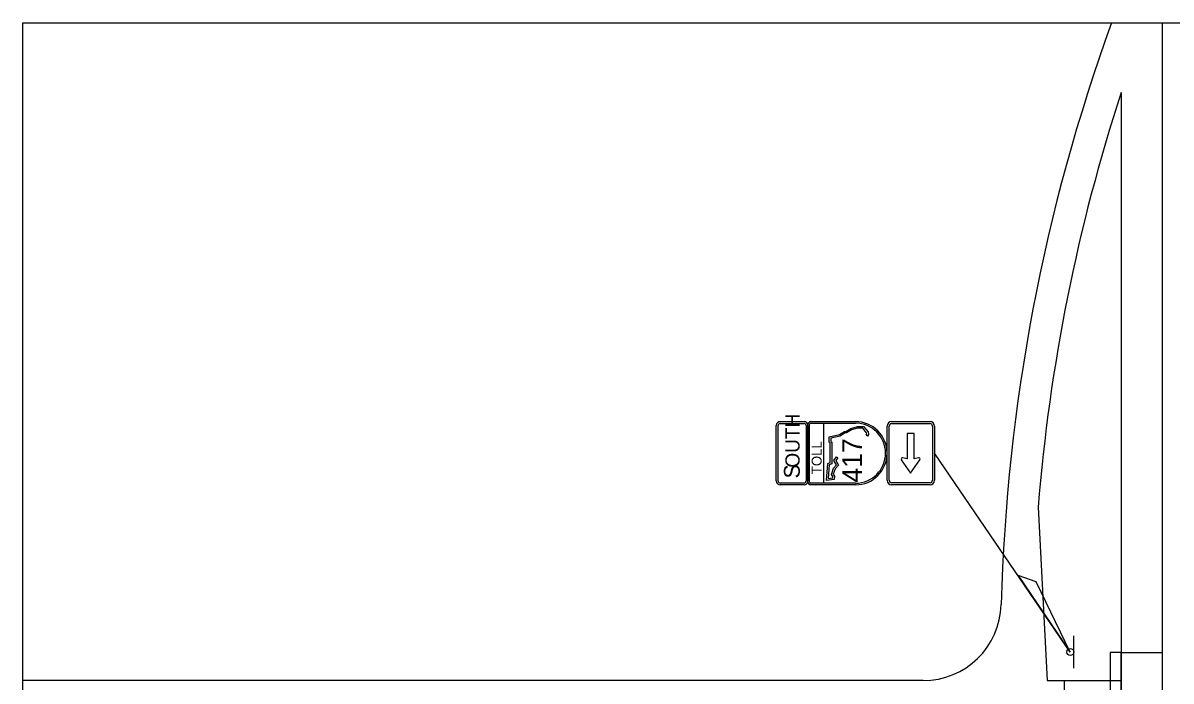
# Model space of a CAD drawing. Extents: x -830008.4 to -829992.7, y 1290284.1 to 1290294.4.
# Drawn here: x -830007.47 to -830000.13, y 1290290.01 to 1290294.23 of the extents above; entities that cross this region are included whole.
import ezdxf

# ---------------------------------------------------------------- set-up
doc = ezdxf.new("R2010")
doc.units = 0
for name, color, linetype in [('LeaderLine_dp', 7, 'Continuous'), ('NonPlottingEle_dp', 7, 'Continuous'), ('SignPanel', 7, 'Continuous'), ('SignSupport', 7, 'Continuous'), ('TextLabel', 7, 'Continuous')]:
    doc.layers.add(name, color=color, linetype=linetype)

msp = doc.modelspace()

# ---------------------------------------------------------------- linework, layer by layer
at = {"layer": 'LeaderLine_dp'}
for p, q in [((-830000.9905, 1290290.6499), (-830001.1075, 1290290.6898)), ((-830001.1075, 1290290.6898), (-830000.7731, 1290290.1996)), ((-830000.7731, 1290290.1996), (-830000.9905, 1290290.6499))]:
    msp.add_line(p, q, dxfattribs=at)
at = {"layer": 'NonPlottingEle_dp'}
msp.add_lwpolyline([(-830007.4742, 1290294.228), (-829992.7742, 1290294.228), (-829992.7742, 1290285.328), (-830007.4742, 1290285.328)], close=True, dxfattribs=at)
at = {"layer": 'SignPanel'}
for p, q in [((-830002.2504, 1290291.5919), (-830002.217, 1290291.6127)), ((-830002.217, 1290291.6127), (-830002.2086, 1290291.6127)), ((-830002.2086, 1290291.6127), (-830002.1776, 1290291.6315)), ((-830002.1734, 1290291.6217), (-830002.2056, 1290291.6021)), ((-830002.1776, 1290291.6315), (-830002.1352, 1290291.6431)), ((-830002.1338, 1290291.6325), (-830002.1734, 1290291.6217)), ((-830002.1352, 1290291.6431), (-830002.0956, 1290291.6431)), ((-830002.1006, 1290291.6325), (-830002.1338, 1290291.6325)), ((-830002.077, 1290291.6037), (-830002.1006, 1290291.6325)), ((-830002.0956, 1290291.6431), (-830002.0673, 1290291.6085)), ((-830002.0673, 1290291.6085), (-830002.0634, 1290291.5921)), ((-830002.3162, 1290291.5766), (-830002.2504, 1290291.5919)), ((-830002.3162, 1290291.5428), (-830002.3162, 1290291.5766)), ((-830002.3092, 1290291.5381), (-830002.3162, 1290291.5428)), ((-830002.3092, 1290291.4127), (-830002.3092, 1290291.5381)), ((-830002.2464, 1290291.582), (-830002.3056, 1290291.5682)), ((-830002.3056, 1290291.5682), (-830002.3056, 1290291.5484)), ((-830002.3056, 1290291.5484), (-830002.2987, 1290291.5437)), ((-830002.2987, 1290291.5437), (-830002.2987, 1290291.4055)), ((-830002.214, 1290291.6021), (-830002.2464, 1290291.582)), ((-830002.2056, 1290291.6021), (-830002.214, 1290291.6021)), ((-830002.0793, 1290291.5877), (-830002.0747, 1290291.5942)), ((-830002.0706, 1290291.5817), (-830002.0793, 1290291.5877)), ((-830002.0747, 1290291.5942), (-830002.077, 1290291.6037)), ((-830002.0634, 1290291.5921), (-830002.0706, 1290291.5817)), ((-830001.8177, 1290291.5985), (-830001.8177, 1290291.4361)), ((-830001.7722, 1290291.5985), (-830001.8177, 1290291.5985)), ((-830001.7722, 1290291.4361), (-830001.7722, 1290291.5985)), ((-830002.3334, 1290291.2972), (-830002.3249, 1290291.4065)), ((-830002.3249, 1290291.4065), (-830002.3092, 1290291.4127)), ((-830002.3149, 1290291.3991), (-830002.3218, 1290291.3097)), ((-830002.2987, 1290291.4055), (-830002.3149, 1290291.3991)), ((-830002.2878, 1290291.3775), (-830002.2686, 1290291.3982)), ((-830002.2851, 1290291.4262), (-830002.2697, 1290291.4491)), ((-830002.2686, 1290291.3982), (-830002.2851, 1290291.4262)), ((-830002.2556, 1290291.3967), (-830002.2785, 1290291.372)), ((-830002.2609, 1290291.4432), (-830002.2727, 1290291.4258)), ((-830002.2727, 1290291.4258), (-830002.2556, 1290291.3967)), ((-830002.2697, 1290291.4491), (-830002.2609, 1290291.4432)), ((-830001.8542, 1290291.4309), (-830001.7949, 1290291.3447)), ((-830001.8177, 1290291.4361), (-830001.8445, 1290291.4441)), ((-830001.7949, 1290291.3447), (-830001.7357, 1290291.4309)), ((-830001.7454, 1290291.4441), (-830001.7722, 1290291.4361)), ((-830002.3218, 1290291.3097), (-830002.2928, 1290291.3142)), ((-830002.3015, 1290291.3353), (-830002.2878, 1290291.3775)), ((-830002.2918, 1290291.3228), (-830002.3015, 1290291.3353)), ((-830002.2928, 1290291.3142), (-830002.2918, 1290291.3228)), ((-830002.2785, 1290291.372), (-830002.2898, 1290291.3374)), ((-830002.2898, 1290291.3374), (-830002.2808, 1290291.3259)), ((-830002.2808, 1290291.3259), (-830002.2833, 1290291.305)), ((-830002.2833, 1290291.305), (-830002.3334, 1290291.2972))]:
    msp.add_line(p, q, dxfattribs=at)
for points in [[(-830002.654, 1290291.2955), (-830002.654, 1290291.6499)], [(-830002.6424, 1290291.2955), (-830002.6424, 1290291.6499)], [(-830002.6287, 1290291.6752), (-830002.4768, 1290291.6752)], [(-830002.6287, 1290291.6636), (-830002.4768, 1290291.6636)], [(-830002.4631, 1290291.6499), (-830002.4631, 1290291.2955)], [(-830002.4515, 1290291.2871), (-830002.4515, 1290291.6583)], [(-830002.4515, 1290291.6499), (-830002.4515, 1290291.2955)], [(-830002.4414, 1290291.2871), (-830002.4414, 1290291.6583)], [(-830002.4346, 1290291.6752), (-830002.1477, 1290291.6752)], [(-830002.4346, 1290291.6651), (-830002.1477, 1290291.6651)], [(-830002.3502, 1290291.2803), (-830002.3502, 1290291.6651)], [(-830001.9452, 1290291.2991), (-830001.9452, 1290291.6463)], [(-830001.932, 1290291.2991), (-830001.932, 1290291.6463)], [(-830001.9163, 1290291.6752), (-830001.6704, 1290291.6752)], [(-830001.9163, 1290291.6619), (-830001.6704, 1290291.6619)], [(-830001.6548, 1290291.6463), (-830001.6548, 1290291.2991)], [(-830001.6415, 1290291.6463), (-830001.6415, 1290291.2991)], [(-830002.4768, 1290291.2818), (-830002.6287, 1290291.2818)], [(-830002.4768, 1290291.2702), (-830002.6287, 1290291.2702)], [(-830002.1477, 1290291.2803), (-830002.4346, 1290291.2803)], [(-830002.1477, 1290291.2702), (-830002.4346, 1290291.2702)], [(-830001.6704, 1290291.2834), (-830001.9163, 1290291.2834)], [(-830001.6704, 1290291.2702), (-830001.9163, 1290291.2702)]]:
    msp.add_lwpolyline(points, dxfattribs=at)
for centre, radius, start, end in [((-830002.6287, 1290291.6499), 0.0253, 90, 180), ((-830002.6287, 1290291.6499), 0.0137, 90, 180), ((-830002.4768, 1290291.6499), 0.0253, 0, 90), ((-830002.4768, 1290291.6499), 0.0137, 0, 90), ((-830002.4346, 1290291.6583), 0.0169, 90, 180), ((-830002.4346, 1290291.6583), 0.00675, 90, 180), ((-830002.1477, 1290291.4727), 0.2025, 270, 90), ((-830002.1477, 1290291.4727), 0.1924, 270, 90), ((-830001.9163, 1290291.6463), 0.0289, 90, 180), ((-830001.9163, 1290291.6463), 0.0157, 90.0544, 180), ((-830001.6704, 1290291.6463), 0.0289, 0, 90), ((-830001.6704, 1290291.6463), 0.0157, 0, 90), ((-830001.847, 1290291.4358), 0.00868, 73.35571, 214.48807), ((-830001.7429, 1290291.4358), 0.00868, 325.51192, 106.64431), ((-830002.6287, 1290291.2955), 0.0253, 180, 270), ((-830002.6287, 1290291.2955), 0.0137, 180, 270), ((-830002.4768, 1290291.2955), 0.0253, 270, 360), ((-830002.4768, 1290291.2955), 0.0137, 270, 360), ((-830002.4346, 1290291.2871), 0.0169, 180, 270), ((-830002.4346, 1290291.2871), 0.00675, 180, 270), ((-830001.9163, 1290291.2991), 0.0289, 180, 270), ((-830001.9163, 1290291.2991), 0.0157, 180, 269.9456), ((-830001.6704, 1290291.2991), 0.0289, 270, 360), ((-830001.6704, 1290291.2991), 0.0157, 270, 360)]:
    msp.add_arc(centre, radius, start, end, dxfattribs=at)
at = {"layer": 'SignSupport'}
msp.add_line((-830000.7511, 1290290.0967), (-830000.7511, 1290290.3025), dxfattribs=at)
msp.add_circle((-830000.7731, 1290290.1996), 0.0221, dxfattribs=at)
at = {"layer": 'TextLabel'}
for p, q in [((-830000.1852, 1290294.228), (-830000.1852, 1290285.328)), ((-830000.448, 1290293.7828), (-830000.448, 1290288.446)), ((-830000.7731, 1290290.1996), (-830001.6415, 1290291.4727)), ((-830000.9789, 1290291.1282), (-830000.922, 1290290.0166)), ((-830000.448, 1290290.196), (-830000.1852, 1290290.196)), ((-830001.7147, 1290290.0166), (-830007.4742, 1290290.0166)), ((-830000.922, 1290290.0166), (-830000.448, 1290290.0166)), ((-830000.8113, 1290290.0166), (-830000.8113, 1290289.8188))]:
    msp.add_line(p, q, dxfattribs=at)
msp.add_lwpolyline([(-830000.448, 1290290.196), (-830000.517, 1290290.196), (-830000.517, 1290289.3342), (-830000.448, 1290289.3342), (-830000.448, 1290290.196)], dxfattribs=at)
msp.add_lwpolyline([(-830000.1852, 1290289.3342), (-830000.448, 1290289.3342), (-830000.448, 1290290.196), (-830000.1852, 1290290.196)], close=True, dxfattribs=at)
for centre, radius, start, end in [((-829989.4075, 1290290.1947), 11.8114, 160.03301, 178.50157), ((-829989.4075, 1290290.1947), 11.6089, 161.99605, 175.38775), ((-830001.7147, 1290290.5166), 0.5, 270, 358.50157)]:
    msp.add_arc(centre, radius, start, end, dxfattribs=at)

# ---------------------------------------------------------------- texts
at = {"layer": 'SignPanel'}
for s, height, p in [('OUTH', 0.09113, (-830002.5049, 1290291.3803)), ('TOLL', 0.06328, (-830002.3642, 1290291.3383)), ('417', 0.12656, (-830002.1055, 1290291.2853)), ('S', 0.1013, (-830002.5038, 1290291.311))]:
    msp.add_text(s, height=height, rotation=90, dxfattribs=at).set_placement(p)

doc.saveas('drawing.dxf')
